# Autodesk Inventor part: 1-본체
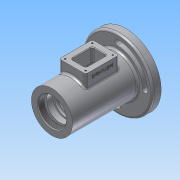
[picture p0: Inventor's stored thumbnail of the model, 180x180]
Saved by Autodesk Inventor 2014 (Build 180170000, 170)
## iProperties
Created: 2017-05
Part Number: 1-본체
Material: Aluminum 6061
Document SubType Name: Modeling
Designer: user
Density: 2.71 g/cm^3
Appearance: Aluminum - Flat
Mass: 717.713 g
Surface Area: 629.341 cm^2
Volume: 264.839 cm^3
Author: user
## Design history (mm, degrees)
sketch "Sketch2"
  geometry: L1 (0, 0)-(115, 0); L2 (0, 0)-(0, 31); L3 (0, 31)-(99, 31); L4 (99, 31)-(99, 53); L5 (99, 53)-(112, 53); L6 (112, 53)-(112, 31); L7 (112, 31)-(115, 31); L8 (115, 31)-(115, 0)
  constraints: 16 end point, 4 parallel, 2 collinear, 2 perpendicular, 1 horizontal
  dimensions: "d0" = 115 distance of L1.start L1.end; "d1" = 3 distance between parallel lines of L8 L6; "d2" = 13 distance of L4.end L5.end; "d3" = 106 diameter of L5 L1; "d4" = 62 diameter of L3 L1
revolve "Revolution1" sketch "Sketch2" stored, may be unused: angle "d5" = 90 deg
workplane "Work Plane1"
sketch "Sketch3"
  geometry: L1 (-81, -20)-(-31, -20); L2 (-31, -20)-(-31, 20); L3 (-31, 20)-(-81, 20); L4 (-81, 20)-(-81, -20); L5 (-81, -20)-(-31, 20); L6 (-31, -20)-(-81, 20); L7 (0, 31)-(0, -31) reference; 4 further points
  constraints: 12 end point, 4 midpoint, 2 parallel, 1 horizontal, 1 horizontal alignment, 1 perpendicular
  dimensions: "d7" = 56 distance from line of L7 point (-56, 0); "d8" = 40 distance of L1.end L2.end; "d9" = 50 distance of L1.start L1.end
extrude "Extrusion1" join sketch "Sketch3" stored distance "d10" = 10; taper "d11" = 0 deg
sketch "Sketch4"
  geometry: L1 (0, -31)-(0, 31) reference; L2 (115, -31)-(115, 31) reference; L3 (0, 0)-(115, 0); L4 (0, 21)-(9, 21); L5 (9, 21)-(9, 24); L6 (9, 24)-(12, 24); L7 (12, 24)-(12, 20); L8 (21, 20)-(21, 17.5); L9 (21, 17.5)-(24.25, 17.5); L10 (24.25, 17.5)-(24.25, 18.5); L11 (24.25, 18.5)-(26, 18.5); L12 (26, 18.5)-(26, 17.5); L13 (26, 17.5)-(37, 17.5); L14 (37, 17.5)-(37, 26); L15 (37, 26)-(75, 26); L16 (75, 26)-(75, 17.5); L17 (75, 17.5)-(86, 17.5); L18 (86, 17.5)-(86, 16.5); L19 (86, 16.5)-(91, 16.5); L20 (91, 16.5)-(91, 10); L21 (91, 10)-(93.7, 10); L22 (93.7, 10)-(93.7, 12.5); L23 (93.7, 12.5)-(100.3, 12.5); L24 (100.3, 12.5)-(101, 12.904); L25 (101, 12.904)-(101, 16); L26 (101, 16)-(115, 22); L27 (12, 20)-(21, 20)
  constraints: 50 end point, 15 parallel, 6 perpendicular, 2 collinear, 2 point on line, 1 midpoint, 1 vertical
  dimensions: "d12" = 42 diameter of L4 L3; "d17" = 3 distance of L5.end L6.end; "d18" = 12 distance between parallel lines of L7 L1; "d19" = 21 distance between parallel lines of L8 L1; "d20" = 26 distance between parallel lines of L12 L1; "d21" = 1.75 distance of L10.end L11.end; "d22" = 38 distance of L14.end L15.end; "d23" = 86 distance between parallel lines of L18 L1; "d24" = 5 distance between parallel lines of L20 L18; "d25" = 14 distance between parallel lines of L25 L2; "d26" = 0.7 horizontal distance of L24.end L23.end; "d27" = 30 deg angle of L23 L24; "d28" = 48 diameter of L6 L3; "d29" = 37 diameter of L11 L3; "d30" = 35 diameter of L9 L3; "d32" = 32 diameter of L25.end L3; "d33" = 44 diameter of L26.end L3; "d34" = 7.3 distance from line of L22 L24.end; "d35" = 20 diameter of L21 L3; "d36" = 25 diameter of L23 L3; "d37" = 33 diameter of L19 L3; "d38" = 52 diameter of L15 L3; "d39" = 11 distance between parallel lines of L12 L14; "d85" = 40 diameter of L27 L3
revolve "Revolution2" sketch "Sketch4" stored, may be unused: angle "d40" = 90 deg
sketch "Sketch5"
  geometry: L1 (-40, -11)-(-72, -11); L2 (-72, -11)-(-72, 11); L3 (-72, 11)-(-40, 11); L4 (-40, 11)-(-40, -11); L5 (-40, -11)-(-72, 11); L6 (-72, -11)-(-40, 11); L7 (-115, 31)-(-115, -31) reference; L8 (0, 31)-(0, -31) reference; 3 further points
  constraints: 12 end point, 3 midpoint, 2 parallel, 1 horizontal, 1 horizontal alignment, 1 perpendicular
  dimensions: "d42" = 32 distance of L2.end L3.end; "d43" = 22 distance of L3.end L1.start; "d44" = 56 distance from line of L8 point (-56, 0)
extrude "Extrusion2" cut sketch "Sketch5" stored distance "d45" = 10; taper "d46" = 0 deg
sketch "Sketch6"
  geometry: L1 (-81, 20)-(-81, -20) reference; L2 (-35.5, -15.5)-(-76.5, -15.5); L3 (-76.5, -15.5)-(-76.5, 15.5); L4 (-76.5, 15.5)-(-35.5, 15.5); L5 (-35.5, 15.5)-(-35.5, -15.5); L6 (-35.5, -15.5)-(-76.5, 15.5); L7 (-76.5, -15.5)-(-35.5, 15.5); L8 (0, 31)-(0, -31) reference; 4 further points
  constraints: 12 end point, 4 midpoint, 2 parallel, 1 horizontal, 1 horizontal alignment, 1 perpendicular
  dimensions: "d47" = 56 distance from line of L8 point (-56, 0); "d48" = 41 distance of L3.end L4.end; "d49" = 31 distance of L4.end L2.start
hole "Hole1" sketch "Sketch6" at (-35.5, 15.5), (-35.5, -15.5), (-76.5, -15.5), (-76.5, 15.5) diameter "d50" = 2.459; stored, may be unused: countersink angle "d54" = 90 deg, drill point angle "d56" = 118 deg; dims "d51" = 6, "d52" = 4, "d53" = 2, "d55" = 8
fillet "Fillet1" dims "d57" = 3
fillet "Fillet2" dims "d58" = 1
fillet "Fillet3" dims "d59" = 3
fillet "Fillet4" dims "d60" = 3
thread "Thread1" dims "d61" = 10, "d62" = 0
chamfer "Chamfer1" distance "d63" = 1; stored, may be unused: second distance "d64" = 2, angle "d65" = 45 deg
sketch "Sketch7"
  geometry: L1 (0, 0)-(45.5, 0); L2 (0, 0)-(0, -45.5); L3 (0, 0)-(-45.5, 0); L4 (0, 0)-(0, 45.5); C1 r 31 at (0, 0) reference; A1 r 41.5 centre (0, 0) between (0, -41.5) and (41.5, 0); A2 r 4 centre (0, -41.5) between (0, -45.5) and (0, -37.5); A3 r 4 centre (41.5, 0) between (37.5, 0) and (45.5, 0); A4 r 4 centre (0, 41.5) between (0, 45.5) and (0, 37.5); A5 r 4 centre (-41.5, 0) between (-37.5, 0) and (-45.5, 0); A6 r 37.5 centre (0, 0) between (-37.5, 0) and (0, -37.5); A7 r 37.5 centre (0, 0) between (37.5, 0) and (0, 37.5); A8 r 45.5 centre (0, 0) between (45.5, 0) and (0, 45.5); A9 r 45.5 centre (0, 0) between (-45.5, 0) and (0, -45.5)
  constraints: 20 point on circle, 9 centre point, 8 end point, 4 point on line, 3 coincident, 3 perpendicular, 2 equal radius, 1 horizontal
  dimensions: "d67" = 83 diameter of A1; "d71" = 4 radius of A5; "d72" = 37.5 radius of A7
extrude "Extrusion3" cut sketch "Sketch7" distance "d73" = 13; taper "d74" = 0 deg
fillet "Fillet5" dims "d75" = 3
fillet "Fillet6" dims "d76" = 0.3
chamfer "Chamfer2" distance "d77" = 1; stored, may be unused: second distance "d78" = 2, angle "d79" = 45 deg
sketch "Sketch8"
  geometry: L1 (44, 0)-(0, 0) reference; L2 (78, 75)-(78, 13) reference; 2 further points
  constraints: 1 other
  dimensions: "d80" = 8 distance from line of point (22, 8) L1; "d81" = 56 distance from line of point (22, 8) L2
emboss "Emboss1" sketch "Sketch8" dims "d82" = 0.5, "d83" = 0
fillet "Fillet7" dims "d84" = 3
body "Solid1"
other parameters: "d6" = 44, "d69" = 75, "d70" = 91
